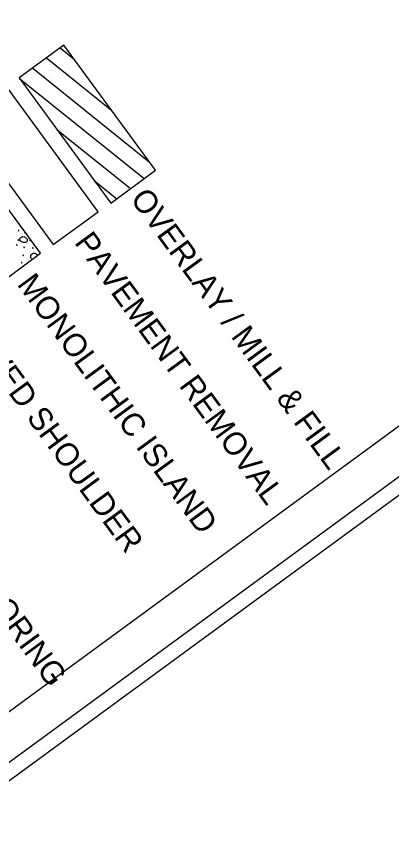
# Model space of a CAD drawing. Extents: x 1762935 to 1764817, y 711157 to 713215.
# Drawn here: x 1763956.3 to 1764070.7, y 711157 to 711407.8 of the extents above; entities that cross this region are included whole.
import ezdxf

# ---------------------------------------------------------------- set-up
doc = ezdxf.new("R2010")
doc.units = 0
for name, color, linetype in [('Matchline', 7, 'Continuous'), ('Old_Level_40', 7, 'Continuous'), ('Prop DSN Text', 7, 'Continuous'), ('Sheet Border Standard 30in CELL', 7, 'Continuous'), ('Sheet Plot Border Inside CELL', 7, 'Continuous'), ('Sheet Plot Border Outside CELL', 7, 'Continuous')]:
    doc.layers.add(name, color=color, linetype=linetype)

msp = doc.modelspace()

# ---------------------------------------------------------------- linework, layer by layer
at = {"layer": 'Matchline'}
for points in [[(1763956.85, 711342.57), (1763956.81, 711342.53), (1763956.91, 711342.42), (1763957.06, 711342.48), (1763957.01, 711342.6), (1763956.93, 711342.59), (1763956.88, 711342.57), (1763956.86, 711342.56)], [(1763957.31, 711343.98), (1763957.27, 711343.95), (1763957.37, 711343.83), (1763957.49, 711343.9), (1763957.5, 711343.92)], [(1763957.44, 711344.01), (1763957.42, 711344.01), (1763957.38, 711344), (1763957.34, 711343.98), (1763957.32, 711343.97)], [(1763958.75, 711341.94), (1763958.71, 711341.91), (1763958.81, 711341.79), (1763958.96, 711341.85), (1763958.91, 711341.97), (1763958.83, 711341.96), (1763958.78, 711341.94), (1763958.76, 711341.93)], [(1763956.73, 711339.68), (1763956.69, 711339.65), (1763956.79, 711339.53), (1763956.94, 711339.59), (1763956.89, 711339.71), (1763956.81, 711339.7), (1763956.76, 711339.68), (1763956.74, 711339.67)], [(1763958.74, 711340.61), (1763958.39, 711340.67), (1763957.78, 711340.68), (1763957.32, 711340.22), (1763957.23, 711339.69), (1763957.33, 711339.35), (1763958.14, 711339), (1763958.79, 711338.8), (1763959.38, 711338.91), (1763959.51, 711339.31), (1763959.67, 711339.71), (1763959.46, 711340.01), (1763959.11, 711340.22), (1763958.83, 711340.5), (1763958.74, 711340.61)], [(1763960.38, 711339.59), (1763960.35, 711339.55), (1763960.44, 711339.43), (1763960.6, 711339.5), (1763960.54, 711339.62), (1763960.46, 711339.6), (1763960.42, 711339.59), (1763960.39, 711339.57)], [(1763956.3, 711338.13), (1763956.26, 711338.09), (1763956.36, 711337.97), (1763956.52, 711338.04), (1763956.46, 711338.16), (1763956.38, 711338.14), (1763956.33, 711338.13), (1763956.31, 711338.11)], [(1763958.5, 711337.41), (1763958.46, 711337.37), (1763958.56, 711337.26), (1763958.71, 711337.32), (1763958.66, 711337.44), (1763958.58, 711337.42), (1763958.53, 711337.41), (1763958.51, 711337.39)], [(1763961.14, 711337.25), (1763961.11, 711337.22), (1763961.2, 711337.1), (1763961.36, 711337.17), (1763961.31, 711337.28), (1763961.22, 711337.27), (1763961.18, 711337.25), (1763961.15, 711337.24)], [(1763958.23, 711335.03), (1763958.19, 711334.99), (1763958.29, 711334.88), (1763958.44, 711334.94), (1763958.39, 711335.06), (1763958.31, 711335.05), (1763958.26, 711335.03), (1763958.24, 711335.02)], [(1763961.03, 711333.69), (1763960.73, 711333.97), (1763960.57, 711334.49), (1763960.76, 711335.29), (1763961.25, 711335.52), (1763961.77, 711335.67), (1763962.38, 711335.44), (1763962.58, 711335.21), (1763962.76, 711334.96)], [(1763957.79, 711332.74), (1763957.75, 711332.7), (1763957.85, 711332.58), (1763958, 711332.65), (1763957.95, 711332.77), (1763957.87, 711332.75), (1763957.82, 711332.73), (1763957.8, 711332.72)]]:
    msp.add_open_spline(points, degree=3, dxfattribs=at)
at = {"layer": 'Old_Level_40'}
for p, q in [((1763969.59, 711398.22), (1763973.97, 711394.69)), ((1763965.41, 711395.16), (1763985.39, 711379.1)), ((1763961.23, 711392.1), (1763996.8, 711363.52)), ((1763957.19, 711388.93), (1763995.25, 711358.35)), ((1763968.6, 711373.35), (1763991.07, 711355.3)), ((1763980.02, 711357.76), (1763986.9, 711352.24))]:
    msp.add_line(p, q, dxfattribs=at)
for points in [[(1763998.72, 711360.9), (1763970.76, 711399.08), (1763957.09, 711389.07), (1763985.05, 711350.89)], [(1763981.17, 711348.24), (1763953.21, 711386.42), (1763939.54, 711376.41), (1763967.5, 711338.23)], [(1763963.61, 711335.58), (1763935.65, 711373.76), (1763921.98, 711363.75), (1763949.94, 711325.57)]]:
    msp.add_lwpolyline(points, close=True, dxfattribs=at)
at = {"layer": 'Sheet Border Standard 30in CELL'}
msp.add_lwpolyline([(1764787.03, 711805.92), (1763900.75, 713016.09), (1763053.63, 712395.69), (1763939.91, 711185.52)], close=True, dxfattribs=at)
at = {"layer": 'Sheet Plot Border Inside CELL'}
msp.add_lwpolyline([(1764796.47, 711797.34), (1763811.81, 713141.84), (1762960.58, 712518.43), (1763945.24, 711173.93)], close=True, dxfattribs=at)
at = {"layer": 'Sheet Plot Border Outside CELL'}
msp.add_lwpolyline([(1764817.24, 711806.98), (1763822.24, 713165.59), (1762934.79, 712515.65), (1763929.78, 711157.04)], close=True, dxfattribs=at)

# ---------------------------------------------------------------- texts
at = {"layer": 'Prop DSN Text'}
for s, p in [('OVERLAY / MILL & FILL', (1763990.79, 711352.17)), ('PAVEMENT REMOVAL', (1763973.73, 711338.83)), ('MONOLITHIC ISLAND', (1763956.23, 711326.1)), ('PAVED SHOULDER', (1763938.81, 711313.26)), ('TEMPORARY SHORING', (1763904.13, 711287.92))]:
    msp.add_text(s, height=7, rotation=306.2176, dxfattribs=at).set_placement(p)

doc.saveas('drawing.dxf')
